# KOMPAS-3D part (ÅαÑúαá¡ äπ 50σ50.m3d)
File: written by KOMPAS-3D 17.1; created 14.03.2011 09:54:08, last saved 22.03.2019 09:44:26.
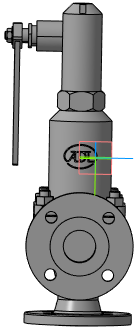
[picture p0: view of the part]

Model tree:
1. Операция без истории:1

Referenced files in D:\Электронный каталог 3d моделей\Предохранительные клапаны Преган\ПРЕГРАН 096\ПРЕГРАН КПП 096-01-16\temp\: Прегран 096 Ду50.a3d
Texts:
  Viktor2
